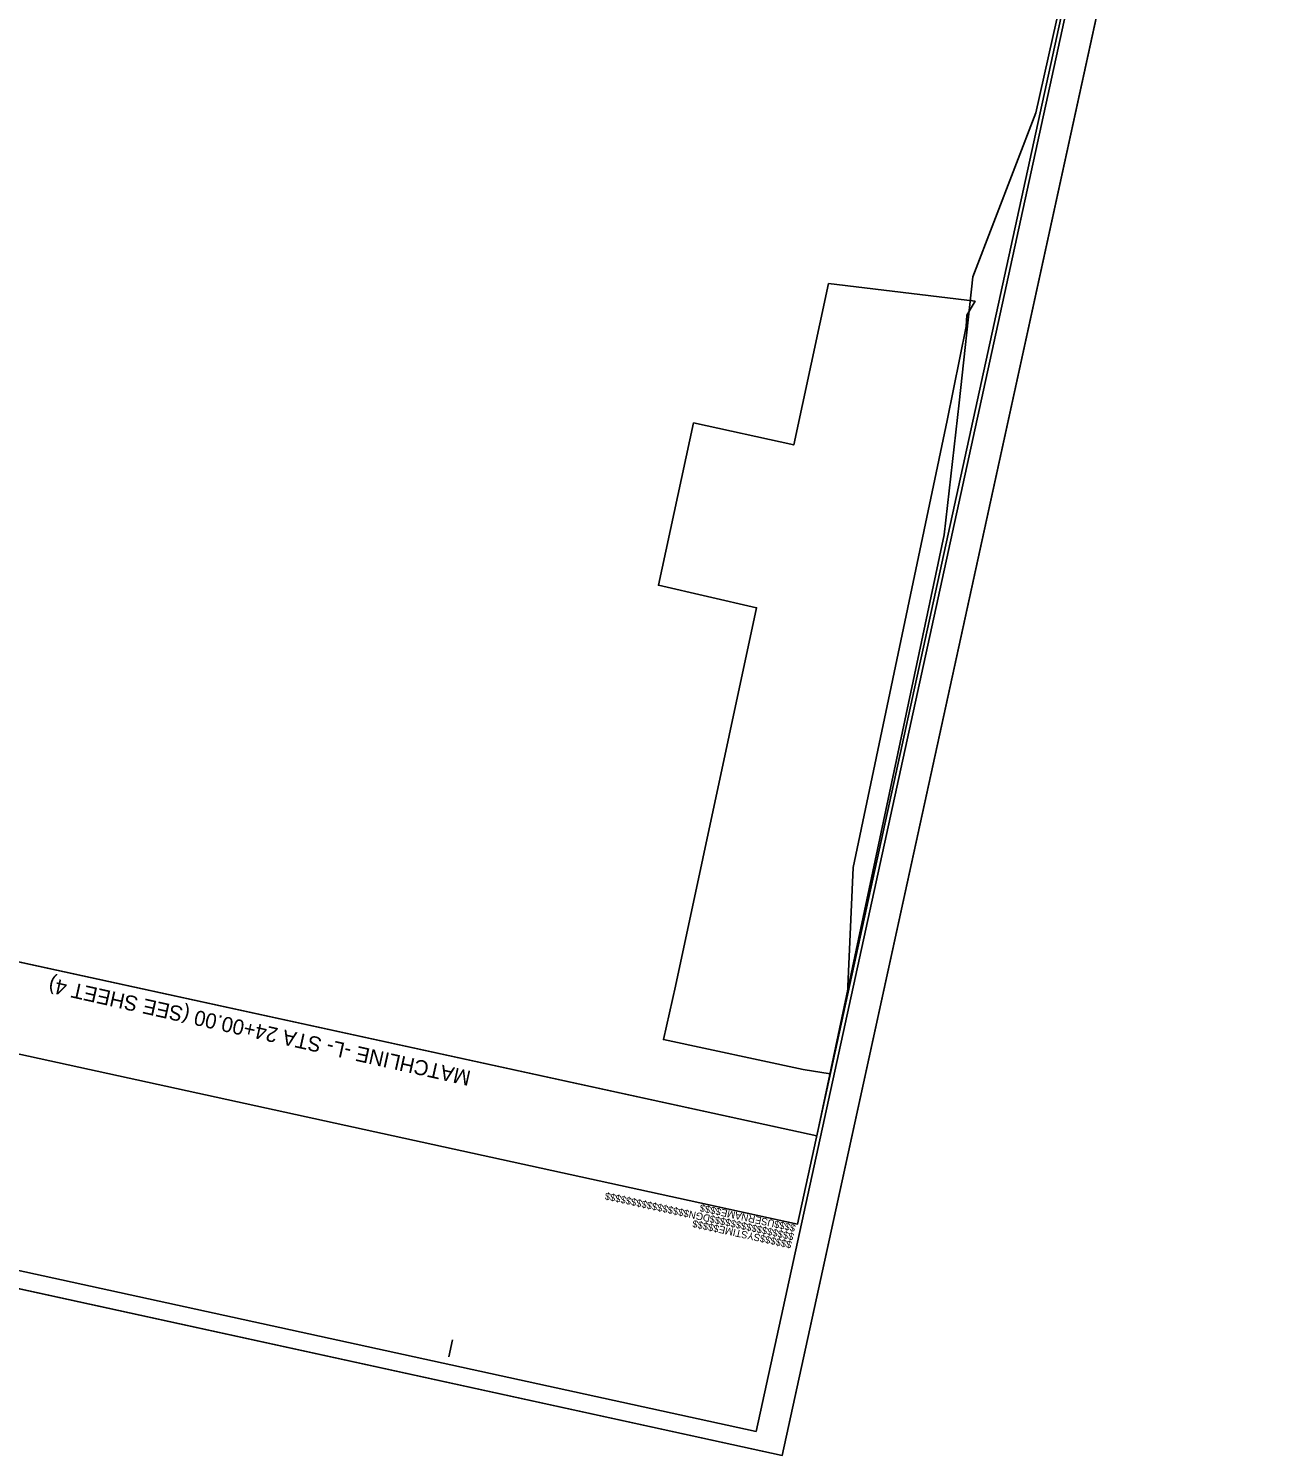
# Model space of a CAD drawing. Extents: x 1615716 to 1617263, y 900664 to 902742.
# Drawn here: x 1616355 to 1617263, y 900664 to 901703 of the extents above; entities that cross this region are included whole.
import ezdxf

# ---------------------------------------------------------------- set-up
doc = ezdxf.new("R2010")
doc.units = 0
for name, color, linetype in [('Exist Structure Minor Pipes RCP 24 Inch', 7, 'Continuous'), ('Prop CMT Slope Cut', 7, 'Continuous'), ('Prop Drainage Structure Plot Symbol 20 Scale', 7, 'Continuous'), ('Prop SS Cut Line', 7, 'Continuous'), ('Prop SS Cut Text', 7, 'Continuous'), ('Prop SS Fill Line', 7, 'Continuous'), ('Prop SS Fill Text', 7, 'Continuous'), ('Scratch_Level_0', 7, 'Continuous')]:
    doc.layers.add(name, color=color, linetype=linetype)

msp = doc.modelspace()

# ---------------------------------------------------------------- linework, layer by layer
at = {"layer": 'Exist Structure Minor Pipes RCP 24 Inch'}
msp.add_lwpolyline([(1616938.4, 900941.9), (1616918.8, 900945.1), (1616817, 900966.9), (1616825.7, 901005.7), (1616884.8, 901281.4), (1616813.3, 901297.8), (1616839, 901416), (1616911.9, 901399.9), (1616937.3, 901517.4), (1617043.9, 901504.6), (1617037.9, 901494.5), (1617037.5, 901486.3), (1617023.7, 901417.7), (1616955.2, 901092.3), (1616951, 901000.1)], close=True, dxfattribs=at)
at = {"layer": 'Prop Drainage Structure Plot Symbol 20 Scale'}
msp.add_lwpolyline([(1616850.4, 902379.9), (1617227.5, 902296.2), (1617121.4, 901790.4), (1617088.2, 901641.8), (1617042.4, 901522.3), (1617032.3, 901430.6), (1617021.4, 901334.4), (1616928.8, 900896.8), (1615902.8, 901120.3), (1615974.3, 901386.7), (1616087.7, 901888.9), (1616145.5, 901879.2), (1616184.1, 901827.5), (1616138.4, 901615), (1616150.6, 901618.1), (1616181.3, 901620.7), (1616299.2, 901764.2), (1616120.1, 901933.3), (1616161.3, 902112.5), (1616179.7, 902310.4), (1616338.6, 902281.4), (1616353.5, 902358.3)], close=True, dxfattribs=at)
at = {"layer": 'Prop SS Cut Line'}
for p, q in [((1616903.5, 900664), (1617262.7, 902309.2)), ((1615828.8, 900898.6), (1616903.5, 900664))]:
    msp.add_line(p, q, dxfattribs=at)
at = {"layer": 'Prop SS Cut Text'}
msp.add_lwpolyline([(1616209, 902534.7), (1615853.6, 900906.5), (1616884.4, 900681.5), (1617239.8, 902309.6)], close=True, dxfattribs=at)
at = {"layer": 'Prop SS Fill Line'}
msp.add_line((1616660.8, 900735.9), (1616663.5, 900748.1), dxfattribs=at)
msp.add_lwpolyline([(1616208.8, 902521.9), (1615888.9, 901056.4), (1616914.7, 900832.5), (1617234.6, 902298)], close=True, dxfattribs=at)
at = {"layer": 'Prop SS Fill Text'}
msp.add_lwpolyline([(1616188, 902543.8), (1615828.8, 900898.6), (1616903.5, 900664), (1617262.7, 902309.2)], close=True, dxfattribs=at)
at = {"layer": 'Scratch_Level_0'}
msp.add_line((1615902.8, 901120.3), (1616928.8, 900896.8), dxfattribs=at)

# ---------------------------------------------------------------- texts
at = {"layer": 'Prop CMT Slope Cut'}
msp.add_text('MATCHLINE -L- STA 24+00.00 (SEE SHEET 4)', height=11, rotation=167.4336, dxfattribs=at).set_placement((1616677.4, 900943.8))
at = {"layer": 'Prop SS Fill Line'}
for s, p in [('$$$$$$$$$$$$$$$$DGN$$$$$$$$$$$$$$$$', (1616912.4, 900825.7)), ('$$$$USERNAME$$$$', (1616913.6, 900831.9)), ('$$$$$$SYSTIME$$$$$', (1616910.9, 900819.8))]:
    msp.add_text(s, height=5.25, rotation=167.6862, dxfattribs=at).set_placement(p)

doc.saveas('drawing.dxf')
